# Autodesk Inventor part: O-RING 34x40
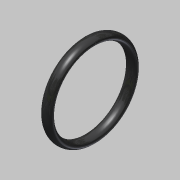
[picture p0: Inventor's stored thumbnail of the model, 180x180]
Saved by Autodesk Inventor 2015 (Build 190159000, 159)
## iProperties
Created: 2020-02
Part Number: O-RING 34x40
Material: 고무
Document SubType Name: Modeling
Designer: mduedu
Density: 1 g/cm^3
Appearance: 고무 - 검은색 - 버전 1.1
Author: mduedu
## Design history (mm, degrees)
sketch "스케치1"
  geometry: L1 (-3.29, 0)-(3.29, 0) reference; L2 (-2.35, 18.5)-(2.35, 18.5); L3 (0, 20)-(0, 17); 6 further points; 1 other entity
  constraints: 4 coincident, 4 end point, 2 horizontal, 2 midpoint, 1 vertical, 1 vertical alignment, 6 other
  dimensions: "d0" = 34 diameter of point (0, 17) L1; "d1" = 40 diameter of point (0, 20) L1; "d2" = 2.35 distance from line of point (2.35, 18.5) L3
revolve "회전1" sketch "스케치1" stored, may be unused: angle "d3" = 90 deg
node "솔리드1"
